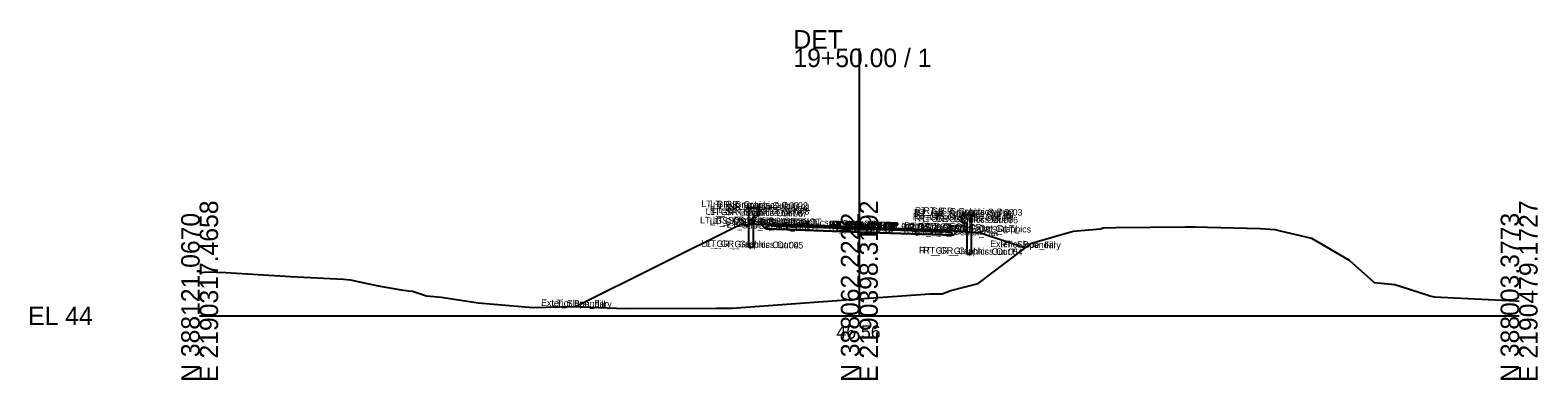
# Model space of a CAD drawing. Extents: x -26 to 1203, y -10 to 9543.
# Drawn here: x -25.7 to 202.8, y 9490.3 to 9543.3 of the extents above; entities that cross this region are included whole.
import ezdxf

# ---------------------------------------------------------------- set-up
doc = ezdxf.new("R2010")
doc.units = 0
for name, color, linetype in [('Default', 7, 'Continuous'), ('Exist Cross Section Cell', 7, 'Continuous'), ('Exist XS Center Line Elevation Label', 7, 'Continuous'), ('Exist XS Ground Line', 7, 'Continuous'), ('Prop CMT Guardrail Graphics', 7, 'Continuous'), ('Prop CMT Pvmt Course 1', 7, 'Continuous'), ('Prop CMT Pvmt Course 2', 7, 'Continuous'), ('Prop CMT Pvmt Course 3', 7, 'Continuous'), ('Prop CMT Pvmt Surface', 7, 'Continuous'), ('Prop CMT Pvmt Surface Shoulder', 7, 'Continuous'), ('Prop CMT Shld Paved Course 1', 7, 'Continuous'), ('Prop CMT Shld Paved Course 2', 7, 'Continuous'), ('Prop CMT Shld Paved Course 3', 7, 'Continuous'), ('Prop CMT Slope Grass', 7, 'Continuous'), ('Prop CMT Subgrade Earthwork', 7, 'Continuous'), ('Scratch_Level_0', 7, 'Continuous')]:
    doc.layers.add(name, color=color, linetype=linetype)

msp = doc.modelspace()

# ---------------------------------------------------------------- linework, layer by layer
at = {"layer": 'Exist Cross Section Cell'}
for p, q in [((100, 9500), (100, 9540.5)), ((0, 9500), (100, 9500)), ((100, 9500), (200, 9500))]:
    msp.add_line(p, q, dxfattribs=at)
at = {"layer": 'Exist XS Ground Line'}
for p, q in [((126.1, 9511.03), (132.42, 9512.85)), ((132.42, 9512.85), (136.54, 9513.21)), ((136.54, 9513.21), (136.94, 9513.33)), ((136.94, 9513.33), (138.85, 9513.41)), ((138.85, 9513.41), (149.42, 9513.49)), ((149.42, 9513.49), (149.8, 9513.5)), ((149.8, 9513.5), (150.79, 9513.48)), ((150.79, 9513.48), (160.76, 9513.26)), ((160.76, 9513.26), (162.97, 9513.07)), ((162.97, 9513.07), (163.76, 9512.89)), ((163.76, 9512.89), (168.53, 9511.76)), ((168.53, 9511.76), (170.72, 9510.53)), ((117.99, 9504.92), (126.1, 9511.03)), ((170.72, 9510.53), (174.24, 9508.43)), ((174.24, 9508.43), (177.46, 9505.58)), ((0, 9506.57), (1.45, 9506.69)), ((1.45, 9506.69), (2.53, 9506.64)), ((2.53, 9506.64), (3.98, 9506.56)), ((3.98, 9506.56), (13.75, 9505.96)), ((13.75, 9505.96), (21.78, 9505.54)), ((21.78, 9505.54), (22.8, 9505.44)), ((22.8, 9505.44), (27.05, 9504.56)), ((113.88, 9503.84), (117.99, 9504.92)), ((177.46, 9505.58), (178.04, 9505.06)), ((178.04, 9505.06), (181.14, 9504.73)), ((181.14, 9504.73), (186.05, 9503.18)), ((27.05, 9504.56), (30.53, 9503.94)), ((30.53, 9503.94), (31.65, 9503.81)), ((31.65, 9503.81), (32.27, 9503.74)), ((32.27, 9503.74), (34.37, 9503.05)), ((34.37, 9503.05), (36.6, 9502.82)), ((36.6, 9502.82), (42.2, 9501.97)), ((80.74, 9501.17), (100, 9502.56)), ((100, 9502.56), (110.68, 9503.33)), ((110.68, 9503.33), (112.56, 9503.35)), ((112.56, 9503.35), (113.88, 9503.84)), ((186.05, 9503.18), (186.49, 9503.05)), ((186.49, 9503.05), (187.1, 9502.91)), ((187.1, 9502.91), (199.45, 9502.28)), ((42.2, 9501.97), (50.56, 9501.29)), ((50.56, 9501.29), (56.51, 9501.42)), ((56.51, 9501.42), (64.48, 9501.11)), ((64.48, 9501.11), (78.31, 9501.16)), ((78.31, 9501.16), (80.74, 9501.17)), ((199.45, 9502.28), (200, 9502.24))]:
    msp.add_line(p, q, dxfattribs=at)
at = {"layer": 'Prop CMT Guardrail Graphics'}
for points in [[(83.24, 9510.35), (83.24, 9516.35)], [(83.24, 9516.35), (84.57, 9516.35), (84.84, 9516.06)], [(84.84, 9515.48), (84.57, 9515.18), (83.91, 9515.18)], [(83.91, 9515.18), (83.91, 9510.35)], [(84.84, 9516.06), (84.57, 9515.77)], [(84.57, 9515.77), (84.84, 9515.48)], [(116.98, 9515.33), (115.64, 9515.33), (115.37, 9515.04)], [(115.37, 9515.04), (115.64, 9514.75)], [(115.64, 9514.75), (115.37, 9514.46)], [(115.37, 9514.46), (115.64, 9514.17), (116.31, 9514.17)], [(116.31, 9514.17), (116.31, 9509.33)], [(116.98, 9509.33), (116.98, 9515.33)], [(83.91, 9510.35), (83.24, 9510.35)], [(116.31, 9509.33), (116.98, 9509.33)]]:
    msp.add_lwpolyline(points, dxfattribs=at)
at = {"layer": 'Prop CMT Pvmt Course 1'}
for points in [[(100, 9513.46), (89, 9513.84)], [(89, 9513.84), (89, 9513.59)], [(89, 9513.59), (100, 9513.21)], [(100, 9513.21), (100, 9513.46)], [(100, 9513.46), (111, 9513.09)], [(100, 9513.21), (100, 9513.46)], [(111, 9512.84), (100, 9513.21)], [(111, 9513.09), (111, 9512.84)]]:
    msp.add_lwpolyline(points, dxfattribs=at)
msp.add_lwpolyline([(100, 9513.21), (100, 9513.34), (100, 9513.34), (100, 9513.21)], close=True, dxfattribs=at)
msp.add_lwpolyline([(100, 9513.21), (100, 9513.34), (100, 9513.34), (100, 9513.21)], close=True, dxfattribs=at)
at = {"layer": 'Prop CMT Pvmt Course 2'}
for points in [[(89, 9513.59), (100, 9513.21)], [(100, 9513.21), (89, 9513.59)], [(89, 9513.59), (89, 9513.59)], [(100, 9513.21), (100, 9513.21)], [(111, 9512.84), (100, 9513.21)], [(100, 9513.21), (100, 9513.21)], [(100, 9513.21), (111, 9512.84)], [(111, 9512.84), (111, 9512.84)]]:
    msp.add_lwpolyline(points, dxfattribs=at)
at = {"layer": 'Prop CMT Pvmt Course 3'}
for points in [[(100, 9513.21), (89, 9513.59)], [(89, 9513.59), (89, 9513.09)], [(89, 9513.09), (100, 9512.71)], [(100, 9512.71), (100, 9513.21)], [(100, 9513.21), (111, 9512.84)], [(100, 9512.71), (100, 9513.21)], [(111, 9512.34), (100, 9512.71)], [(111, 9512.84), (111, 9512.34)]]:
    msp.add_lwpolyline(points, dxfattribs=at)
at = {"layer": 'Prop CMT Pvmt Surface'}
for points in [[(100, 9513.46), (89, 9513.84)], [(100, 9513.46), (111, 9513.09)]]:
    msp.add_lwpolyline(points, dxfattribs=at)
at = {"layer": 'Prop CMT Pvmt Surface Shoulder'}
for points in [[(89, 9513.84), (87, 9513.91)], [(111, 9513.09), (113, 9513.02)]]:
    msp.add_lwpolyline(points, dxfattribs=at)
at = {"layer": 'Prop CMT Shld Paved Course 1'}
for points in [[(89, 9513.84), (87, 9513.91), (86.76, 9513.66)], [(89, 9513.59), (89, 9513.84)], [(86.76, 9513.66), (89, 9513.59)], [(111, 9513.09), (113, 9513.02), (113.26, 9512.76)], [(111, 9512.84), (111, 9513.09)], [(113.26, 9512.76), (111, 9512.84)]]:
    msp.add_lwpolyline(points, dxfattribs=at)
at = {"layer": 'Prop CMT Shld Paved Course 2'}
for points in [[(89, 9513.59), (86.76, 9513.66)], [(86.76, 9513.66), (86.76, 9513.66)], [(86.76, 9513.66), (89, 9513.59)], [(89, 9513.59), (89, 9513.59)], [(111, 9512.84), (113.26, 9512.76)], [(113.26, 9512.76), (111, 9512.84)], [(111, 9512.84), (111, 9512.84)], [(113.26, 9512.76), (113.26, 9512.76)]]:
    msp.add_lwpolyline(points, dxfattribs=at)
at = {"layer": 'Prop CMT Shld Paved Course 3'}
for points in [[(89, 9513.59), (86.76, 9513.66), (86.26, 9513.68), (85.77, 9513.2)], [(85.77, 9513.2), (89, 9513.09)], [(89, 9513.09), (89, 9513.59)], [(111, 9512.84), (113.26, 9512.76), (113.76, 9512.75), (114.28, 9512.23)], [(111, 9512.34), (111, 9512.84)], [(114.28, 9512.23), (111, 9512.34)]]:
    msp.add_lwpolyline(points, dxfattribs=at)
at = {"layer": 'Prop CMT Slope Grass'}
for points in [[(84.84, 9513.85), (81.84, 9513.77)], [(87, 9513.91), (84.84, 9513.85)], [(81.84, 9513.77), (57.09, 9501.4)], [(113, 9513.02), (115.37, 9512.83)], [(115.37, 9512.83), (118.37, 9512.59)], [(118.37, 9512.59), (125.16, 9510.33)]]:
    msp.add_lwpolyline(points, dxfattribs=at)
at = {"layer": 'Prop CMT Subgrade Earthwork'}
for points in [[(85.77, 9513.2), (85.12, 9513.86)], [(89, 9513.09), (85.77, 9513.2)], [(100, 9512.71), (89, 9513.09)], [(100, 9512.71), (111, 9512.34)], [(111, 9512.34), (114.28, 9512.23)], [(114.28, 9512.23), (114.92, 9512.87)]]:
    msp.add_lwpolyline(points, dxfattribs=at)

# ---------------------------------------------------------------- texts
at = {"layer": 'Default'}
msp.add_text('-', height=0.0001, dxfattribs=at).set_placement((0, 9500))
at = {"layer": 'Exist Cross Section Cell'}
for s, p in [('DET', (90, 9540.5)), ('19+50.00 / 1', (90, 9537.7)), ('EL 44', (-26, 9498.6))]:
    msp.add_text(s, height=2.8, dxfattribs=at).set_placement(p)
for s, p in [('E 2190317.4658', (2.8, 9490)), ('E 2190398.3192', (102.8, 9490)), ('E 2190479.1727', (202.8, 9490)), ('N 388121.0670', (0, 9490)), ('N 388062.2222', (100, 9490)), ('N 388003.3773', (200, 9490))]:
    msp.add_text(s, height=2.8, rotation=90, dxfattribs=at).set_placement(p)
at = {"layer": 'Exist XS Center Line Elevation Label'}
msp.add_text('46.56', height=2, dxfattribs=at).set_placement((96.52, 9496.56))
at = {"layer": 'Scratch_Level_0'}
for s, p in [('LT_GR_Graphics Out 03', (76.03, 9516.49)), ('LT_GR_Graphics Out 06', (76.68, 9515.32)), ('LT_GR_Graphics Out 07', (77.33, 9515.32)), ('LT_GR_Graphics Out 09', (77.35, 9515.91)), ('LT_GR_Graphics Out 02', (77.38, 9516.49)), ('LT_GR_Graphics Out 08', (77.62, 9515.62)), ('LT_GR_Graphics Out 01', (77.79, 9516.2)), ('RT_GR_Graphics Out 01', (108.26, 9515.18)), ('RT_GR_Graphics Out 02', (108.39, 9515.47)), ('RT_GR_Graphics Out 03', (109.7, 9515.47)), ('LT_GS_OS_GR_Face_Graphics', (75.84, 9514.03)), ('LT_GS_OS_CTL', (77.31, 9513.86)), ('LT_Sub_Trench_Out_DLT', (77.77, 9514)), ('LT_Sub_Trench_Out', (79.89, 9513.31)), ('LT_PS3_Shelf_Out', (80.92, 9513.79)), ('LT_PS3_OEOP', (82.55, 9513.75)), ('LT_PS2_OEOP', (82.55, 9513.75)), ('LT_PS1_OEOP', (82.91, 9513.99)), ('LT_PV2_OEOT', (84.75, 9513.67)), ('LT_PV3_OEOT', (84.75, 9513.67)), ('LT_Sub_OEOT', (84.77, 9513.17)), ('LT_PV1_OEOT', (84.87, 9513.92)), ('RT_PV2_OEEOP', (95.33, 9513.31)), ('RT_PV3_OEEOP', (95.33, 9513.31)), ('LT_PV2_OEEOP', (95.39, 9513.3)), ('LT_PV3_OEEOP', (95.39, 9513.3)), ('RT_PV1_OEEOP', (95.45, 9513.43)), ('LT_PV1_OEEOP', (95.51, 9513.43)), ('RT_PV2_IEEOP', (95.71, 9513.3)), ('LT_PV2_IEEOP', (95.77, 9513.3)), ('RT_PV1_IEEOP', (95.83, 9513.42)), ('LT_PV1_IEEOP', (95.89, 9513.42)), ('PV2_PGL', (97.35, 9513.27)), ('PV1_PGL', (97.47, 9513.51)), ('RT_GS_OS_GR_Face_Graphics', (106.31, 9513.01)), ('RT_PV3_OEOT', (106.69, 9512.92)), ('RT_PV2_OEOT', (106.69, 9512.92)), ('RT_PV1_OEOT', (106.81, 9513.17)), ('RT_Sub_Trench_Out_DLT', (107.51, 9513.01)), ('RT_GR_Graphics Out 08', (108.09, 9514.6)), ('RT_GR_Graphics Out 07', (108.34, 9514.31)), ('RT_GR_Graphics Out 09', (108.36, 9514.89)), ('RT_PS3_Shelf_Out', (108.36, 9512.85)), ('RT_PS1_OEOP', (108.85, 9513.1)), ('RT_PS3_OEOP', (108.99, 9512.85)), ('RT_PS2_OEOP', (108.99, 9512.85)), ('RT_GR_Graphics Out 06', (109.02, 9514.31)), ('RT_Sub_OEEOP', (95.36, 9512.8)), ('LT_Sub_OEEOP', (95.42, 9512.8)), ('RT_Sub_OEOT', (106.71, 9512.42)), ('RT_Sub_Trench_Out', (108.33, 9512.34)), ('RT_GS_OS_CTL', (113.78, 9512.68)), ('LT_GR_Graphics Out 04', (76.01, 9510.49)), ('LT_GR_Graphics Out 05', (76.69, 9510.49)), ('RT_GR_Graphics Out 05', (109.03, 9509.47)), ('RT_GR_Graphics Out 04', (109.69, 9509.47)), ('Exterior Boundary', (119.82, 9510.43)), ('RT_Slope_Fill', (121.34, 9510.4)), ('Exterior Boundary', (51.75, 9501.5)), ('LT_Slope_Fill', (53.33, 9501.47))]:
    msp.add_text(s, height=1, rotation=358.8836, dxfattribs=at).set_placement(p)

doc.saveas('drawing.dxf')
